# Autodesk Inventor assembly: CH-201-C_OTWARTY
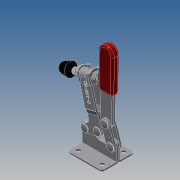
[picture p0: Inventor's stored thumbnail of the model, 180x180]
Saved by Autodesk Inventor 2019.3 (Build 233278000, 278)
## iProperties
Company: ·L?¤¤?
Created: 2010-06
Part Number: CH-201-C_OTWARTY
Material: Ogólny
Description: STEP AP203
Document SubType Name: Assembly
Designer: CADENGINEERING4
Sending System: SolidWorks 2005179
Preprocessor: SwSTEP 2.0
Title: CH-201-C.STEP
Author: ·L?¥Î?
Revision Number: ANY
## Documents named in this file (10)
- E:\STRONA\Horizontal toggle clamp\CH-201-C\CH-201-C_OTWARTY.iam
- E:\STRONA\Horizontal toggle clamp\CH-201-C\201-C-02___.ipt
- E:\STRONA\Horizontal toggle clamp\CH-201-C\201-C-06___.ipt
- E:\STRONA\Horizontal toggle clamp\CH-201-C\201-C-03___.ipt
- E:\STRONA\Horizontal toggle clamp\CH-201-C\14134-01___.ipt
- E:\STRONA\Horizontal toggle clamp\CH-201-C\201-C-04___.ipt
- E:\STRONA\Horizontal toggle clamp\CH-201-C\201-C-05___.ipt
- E:\STRONA\Horizontal toggle clamp\CH-201-C\FW140___.ipt
- E:\STRONA\Horizontal toggle clamp\CH-201-C\201-C-01___.ipt
- E:\STRONA\Horizontal toggle clamp\CH-201-C\14134___.ipt
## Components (15 placed, 15 different names)
1. 201-C-02_??_1 — Równoległe:1, Zestawiające:10, Zestawiające:11, Zestawiające:12, Zestawiające:23, Zestawiające:24, Zestawiające:25, Zestawiające:28, Zestawiające:30
2. 201-C-06_??_2 — Zestawiające:22, Zestawiające:23, Zestawiające:25
3. 201-C-03_??_3 — Zestawiające:1, Zestawiające:2, Zestawiające:3, Zestawiające:26, Zestawiające:27, Zestawiające:29, Kątowe:1
4. 14134-01_??_4 — Równoległe:3, Zestawiające:5, Zestawiające:9
5. 201-C-04_??_5 — Zestawiające:13, Zestawiające:16, Zestawiające:17
6. 201-C-05_??_6 — Zestawiające:1, Zestawiające:2, Zestawiające:3
7. 201-C-06_??_7 — Zestawiające:28, Zestawiające:29, Zestawiające:30
8. FW140_??_8 — Równoległe:1, Równoległe:2, Zestawiające:6, Zestawiające:9, Zestawiające:10
9. FW140_??_9 — Równoległe:2, Zestawiające:4, Zestawiające:8, Zestawiające:11
10. 201-C-06_??_10 — Zestawiające:20, Zestawiające:21, Zestawiające:27
11. 201-C-01_??_11 — Zestawiające:13, Zestawiające:14, Zestawiające:15, Zestawiające:16, Zestawiające:22, Zestawiające:24, Kątowe:1
12. 201-C-06_??_12 — Zestawiające:18, Zestawiające:19
13. 201-C-04_??_13 — Zestawiające:14, Zestawiające:15, Zestawiające:17, Zestawiające:18, Zestawiające:19, Zestawiające:20, Zestawiające:21, Zestawiające:26
14. 14134-01_??_14 — Zestawiające:7, Zestawiające:8
15. 14134_??_15 — Równoległe:3, Zestawiające:4, Zestawiające:5, Zestawiające:6, Zestawiające:7, Zestawiające:12
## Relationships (34: Mate 30, Flush 3, Angle 1)
- Równoległe:1 [Flush]: 201-C-02_??_1 ↔ FW140_??_8
- Równoległe:2 [Flush]: FW140_??_8 ↔ FW140_??_9
- Równoległe:3 [Flush]: 14134-01_??_4 ↔ 14134_??_15
- Zestawiające:1 [Mate]: 201-C-03_??_3 ↔ 201-C-05_??_6
- Zestawiające:2 [Mate]: 201-C-03_??_3 ↔ 201-C-05_??_6
- Zestawiające:3 [Mate]: 201-C-03_??_3 ↔ 201-C-05_??_6
- Zestawiające:4 [Mate]: FW140_??_9 ↔ 14134_??_15
- Zestawiające:5 [Mate]: 14134-01_??_4 ↔ 14134_??_15
- Zestawiające:6 [Mate]: FW140_??_8 ↔ 14134_??_15
- Zestawiające:7 [Mate]: 14134-01_??_14 ↔ 14134_??_15
- Zestawiające:8 [Mate]: FW140_??_9 ↔ 14134-01_??_14
- Zestawiające:9 [Mate]: 14134-01_??_4 ↔ FW140_??_8
- Zestawiające:10 [Mate]: 201-C-02_??_1 ↔ FW140_??_8
- Zestawiające:11 [Mate]: 201-C-02_??_1 ↔ FW140_??_9
- Zestawiające:12 [Mate]: 201-C-02_??_1 ↔ 14134_??_15
- Zestawiające:13 [Mate]: 201-C-04_??_5 ↔ 201-C-01_??_11
- Zestawiające:14 [Mate]: 201-C-01_??_11 ↔ 201-C-04_??_13
- Zestawiające:15 [Mate]: 201-C-01_??_11 ↔ 201-C-04_??_13
- Zestawiające:16 [Mate]: 201-C-04_??_5 ↔ 201-C-01_??_11
- Zestawiające:17 [Mate]: 201-C-04_??_5 ↔ 201-C-04_??_13
- Zestawiające:18 [Mate]: 201-C-06_??_12 ↔ 201-C-04_??_13
- Zestawiające:19 [Mate]: 201-C-06_??_12 ↔ 201-C-04_??_13
- Zestawiające:20 [Mate]: 201-C-06_??_10 ↔ 201-C-04_??_13
- Zestawiające:21 [Mate]: 201-C-06_??_10 ↔ 201-C-04_??_13
- Zestawiające:22 [Mate]: 201-C-06_??_2 ↔ 201-C-01_??_11
- Zestawiające:23 [Mate]: 201-C-02_??_1 ↔ 201-C-06_??_2
- Zestawiające:24 [Mate]: 201-C-02_??_1 ↔ 201-C-01_??_11
- Zestawiające:25 [Mate]: 201-C-02_??_1 ↔ 201-C-06_??_2
- Zestawiające:26 [Mate]: 201-C-03_??_3 ↔ 201-C-04_??_13
- Zestawiające:27 [Mate]: 201-C-03_??_3 ↔ 201-C-06_??_10
- Zestawiające:28 [Mate]: 201-C-02_??_1 ↔ 201-C-06_??_7
- Zestawiające:29 [Mate]: 201-C-03_??_3 ↔ 201-C-06_??_7
- Zestawiające:30 [Mate]: 201-C-02_??_1 ↔ 201-C-06_??_7
- Kątowe:1 [Angle]: 201-C-03_??_3 ↔ 201-C-01_??_11
